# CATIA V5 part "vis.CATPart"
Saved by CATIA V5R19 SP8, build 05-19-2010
Part number: vis
Bounding box of the stored display mesh (mm): x -5.992 to 5.992, y -2 to 298, z -5.91 to 5.91
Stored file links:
  G:\EU_thinkMotion\CFAO_2010\MMS_groupe3\MMS_groupe3\A reprendre\mmugnier\Systeme_Cric_Y\Systeme_Cric_Y\vis.CATPart
  C:\Users\matthieu\Desktop\CFAO\Systeme_Cric_Y\Cric_Y.CATProduct
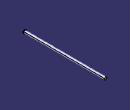
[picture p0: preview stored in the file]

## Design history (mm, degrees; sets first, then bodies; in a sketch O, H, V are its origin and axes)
Set1
  Plane1: linked copy from another document
Body1 (main body)
  Sketch1 on Plane1, origin (0, 0, 0), H (1, 0, 0), V (0, 1, 0)
    point P1 (0, 298)
    line L1 (0, 298) -> (0, -2)
    line L2 (0, -2) -> (6, -2)
    line L3 (6, -2) -> (6, 0)
    point P4 (6, 0)
    line L4 (6, 0) -> (5, 0)
    line L5 (5, 0) -> (5, 298)
    line L6 (5, 298) -> (0, 298)
    length L4 = 1
    distance L1 L5 = 5
    length L3 = 2
    length L1 = 300
    coincidence: P1 V, P4 H
    vertical: L1 V, L3 V, L5 V
    horizontal: L2 H, L4 H, L6 H
  Shaft1: profile Sketch1, axis Sketch1.L1, angle 360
